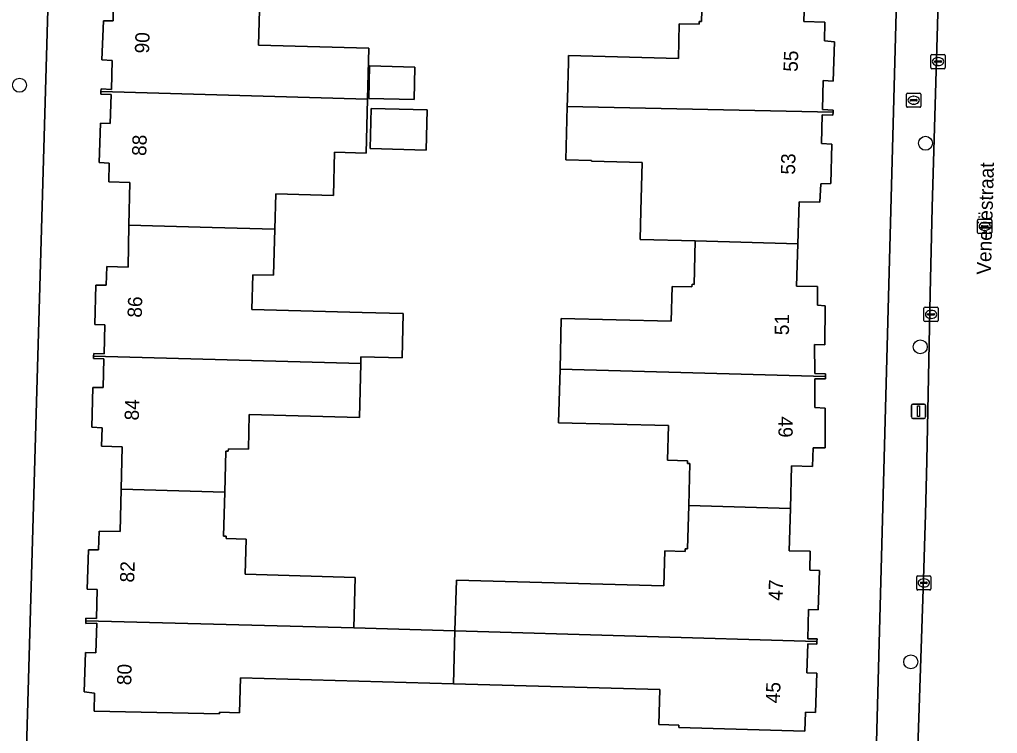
# Model space of a CAD drawing. Extents: x 162082 to 163401, y 388089 to 388636.
# Drawn here: x 162541.9 to 162610.5, y 388380 to 388430.1 of the extents above; entities that cross this region are included whole.
import ezdxf

# ---------------------------------------------------------------- set-up
doc = ezdxf.new("R2010")
doc.units = 0
for name, color, linetype in [('IMGEO_Boom', 7, 'Continuous'), ('IMGEO_Brandkraan', 7, 'Continuous'), ('IMGEO_Erf', 7, 'Continuous'), ('IMGEO_Kolk', 7, 'Continuous'), ('IMGEO_Lichtmast', 7, 'Continuous'), ('IMGEO_Openbare_ruimte_label', 7, 'Continuous'), ('IMGEO_Pand', 7, 'Continuous'), ('IMGEO_Pand_nummerreeks', 7, 'Continuous'), ('IMGEO_Rijbaan_lokaal_open', 7, 'Continuous'), ('IMGEO_Rioolput', 7, 'Continuous'), ('IMGEO_Voetpad_open', 7, 'Continuous')]:
    doc.layers.add(name, color=color, linetype=linetype)

msp = doc.modelspace()

# ---------------------------------------------------------------- linework, layer by layer
at = {"layer": 'IMGEO_Boom'}
for centre in [(162541.9, 388425.468), (162605.489, 388421.397), (162605.12, 388407.11), (162604.452, 388385.007)]:
    msp.add_circle(centre, 0.489, dxfattribs=at)
at = {"layer": 'IMGEO_Brandkraan'}
for p, q in [((162604.158, 388423.994), (162604.158, 388424.846)), ((162604.233, 388424.92), (162605.085, 388424.92)), ((162605.159, 388424.846), (162605.159, 388423.994)), ((162604.417, 388424.414), (162604.417, 388424.426)), ((162604.855, 388424.377), (162604.457, 388424.377)), ((162604.46, 388424.463), (162604.858, 388424.463)), ((162604.669, 388424.14), (162604.644, 388424.14)), ((162604.646, 388424.7), (162604.671, 388424.7)), ((162604.901, 388424.426), (162604.901, 388424.414)), ((162605.085, 388423.92), (162604.233, 388423.92))]:
    msp.add_line(p, q, dxfattribs=at)
for points in [[(162604.158, 388423.994), (162604.158, 388424.846)], [(162604.233, 388424.92), (162605.085, 388424.92)], [(162605.159, 388424.846), (162605.159, 388423.994)], [(162605.085, 388423.92), (162604.233, 388423.92)]]:
    msp.add_lwpolyline(points, dxfattribs=at)
for centre, radius, start, end in [((162604.235, 388424.844), 0.0765, 91.55205, 178.44795), ((162604.235, 388424.844), 0.0765, 91.55205, 178.44795), ((162605.083, 388424.844), 0.0765, 1.55205, 88.44795), ((162605.083, 388424.844), 0.0765, 1.55205, 88.44795), ((162604.457, 388424.423), 0.0403, 85.87752, 175.75265), ((162604.454, 388424.413), 0.0366, 178.93798, 274.71019), ((162604.858, 388424.42), 0.043, 264.86636, 352.45326), ((162604.862, 388424.425), 0.0386, 1.73085, 96.63898), ((162604.235, 388423.996), 0.0765, 181.55205, 268.44795), ((162604.235, 388423.996), 0.0765, 181.55205, 268.44795), ((162605.083, 388423.996), 0.0765, 271.55205, 358.44795), ((162605.083, 388423.996), 0.0765, 271.55205, 358.44795)]:
    msp.add_arc(centre, radius, start, end, dxfattribs=at)
for centre, major_axis, ratio, start_param, end_param in [((162604.645, 388424.42), (-0.387, 0.002), 0.722429, 4.712389, 7.853982), ((162604.67, 388424.42), (-0.39, 0.002), 0.717154, 1.570796, 4.712389)]:
    msp.add_ellipse(centre, major_axis=major_axis, ratio=ratio, start_param=start_param, end_param=end_param, dxfattribs=at)
at = {"layer": 'IMGEO_Erf'}
for points in [[(162544.566, 388454.63), (162544.543, 388453.83), (162544.152, 388440.133), (162546.495, 388440.044), (162546.386, 388437.172), (162546.278, 388437.177), (162544.069, 388437.261), (162542.31, 388375.7), (162595.542, 388374.322), (162601.897, 388374.162), (162603.561, 388435.824)], [(162558.751, 388430.743), (162558.688, 388428.274), (162566.425, 388428.075), (162566.332, 388424.483), (162566.235, 388420.706), (162564.014, 388420.763), (162563.937, 388417.737), (162559.886, 388417.841), (162559.823, 388415.372), (162559.74, 388412.135), (162558.284, 388412.172), (162558.221, 388409.732), (162565.948, 388409.534), (162568.841, 388409.46), (162568.761, 388406.343), (162565.868, 388406.417), (162565.856, 388405.943), (162565.759, 388402.165), (162558.031, 388402.363), (162557.969, 388399.924), (162556.565, 388399.96), (162556.56, 388399.791), (162556.391, 388399.795), (162556.315, 388396.911), (162556.233, 388393.829), (162556.403, 388393.824), (162556.398, 388393.655), (162557.805, 388393.615), (162557.735, 388391.16), (162565.469, 388390.94), (162565.369, 388387.387), (162572.464, 388387.186), (162572.565, 388390.749), (162587.135, 388390.335), (162587.205, 388392.79), (162588.612, 388392.75), (162588.617, 388392.94), (162588.787, 388392.935), (162588.868, 388395.974), (162588.946, 388398.923), (162588.778, 388398.927), (162588.783, 388399.115), (162587.389, 388399.151), (162587.452, 388401.593), (162579.741, 388401.791), (162579.838, 388405.546), (162579.929, 388409.106), (162587.64, 388408.908), (162587.702, 388411.35), (162589.096, 388411.314), (162589.101, 388411.502), (162589.249, 388411.498), (162589.327, 388414.542), (162585.464, 388414.642), (162585.517, 388416.659), (162585.604, 388420.057), (162582.052, 388420.148), (162582.053, 388420.191), (162580.254, 388420.237), (162580.35, 388423.989), (162580.363, 388424.509), (162580.43, 388427.096), (162580.442, 388427.552), (162588.143, 388427.355), (162588.206, 388429.786), (162589.609, 388429.75), (162589.614, 388429.938), (162589.772, 388429.934), (162589.853, 388433.068)], [(162597.041, 388432.876), (162596.948, 388429.933), (162598.43, 388429.889), (162598.393, 388428.574), (162599.107, 388428.521), (162599.013, 388425.762), (162598.301, 388425.792), (162598.262, 388423.766), (162599, 388423.726), (162598.998, 388423.582), (162598.995, 388423.376), (162598.247, 388423.387), (162598.189, 388421.38), (162598.905, 388421.327), (162598.838, 388418.577), (162598.134, 388418.548), (162598.083, 388417.263), (162596.619, 388417.279), (162596.53, 388414.338), (162596.44, 388411.373), (162597.911, 388411.352), (162597.898, 388410.048), (162598.438, 388410), (162598.422, 388407.257), (162597.709, 388407.267), (162597.727, 388405.24), (162598.466, 388405.221), (162598.469, 388405.026), (162598.471, 388404.871), (162597.723, 388404.861), (162597.721, 388402.853), (162598.438, 388402.82), (162598.449, 388400.023), (162597.6, 388400.025), (162597.566, 388398.728), (162596.09, 388398.772), (162596.008, 388395.77), (162595.928, 388392.808), (162597.388, 388392.771), (162597.359, 388391.438), (162598.038, 388391.42), (162597.965, 388388.664), (162597.285, 388388.682), (162597.23, 388386.635), (162597.878, 388386.617), (162597.873, 388386.428), (162597.868, 388386.258), (162597.219, 388386.275), (162597.164, 388384.229), (162597.862, 388384.209), (162597.767, 388381.446), (162597.069, 388381.476), (162597.019, 388380.15), (162588.176, 388380.397), (162588.179, 388380.575), (162586.769, 388380.62), (162586.847, 388383.068), (162572.359, 388383.468), (162557.425, 388383.881), (162557.354, 388381.43), (162555.946, 388381.474), (162555.937, 388381.351), (162547.136, 388381.552), (162547.178, 388382.821), (162546.449, 388382.906), (162546.53, 388385.656), (162547.257, 388385.634), (162547.323, 388387.713), (162546.568, 388387.707), (162546.57, 388387.893), (162546.571, 388388.068), (162547.301, 388388.041), (162547.353, 388390.098), (162546.656, 388390.115), (162546.738, 388392.871), (162547.458, 388392.87), (162547.491, 388394.185), (162548.968, 388394.161), (162549.039, 388397.121), (162549.111, 388400.105), (162547.671, 388400.134), (162547.699, 388401.433), (162546.98, 388401.478), (162547.063, 388404.249), (162547.778, 388404.261), (162547.82, 388406.27), (162547.095, 388406.284), (162547.108, 388406.459), (162547.121, 388406.642), (162547.839, 388406.619), (162547.898, 388408.652), (162547.188, 388408.692), (162547.268, 388411.449), (162547.979, 388411.443), (162548.027, 388412.753), (162549.525, 388412.704), (162549.585, 388415.657), (162549.646, 388418.636), (162548.178, 388418.7), (162548.209, 388420.009), (162547.501, 388420.042), (162547.585, 388422.798), (162548.279, 388422.791), (162548.346, 388424.823), (162547.609, 388424.849), (162547.619, 388425.03), (162547.629, 388425.208), (162548.37, 388425.172), (162548.417, 388427.197), (162547.694, 388427.257), (162547.792, 388429.997), (162548.49, 388429.979), (162548.51, 388431.334)]]:
    msp.add_lwpolyline(points, dxfattribs=at)
for points in [[(162566.416, 388424.547), (162566.475, 388426.83), (162569.655, 388426.748), (162569.596, 388424.465)], [(162566.507, 388421.024), (162566.58, 388423.844), (162570.509, 388423.743), (162570.437, 388420.923)]]:
    msp.add_lwpolyline(points, close=True, dxfattribs=at)
at = {"layer": 'IMGEO_Kolk'}
for p, q in [((162605.867, 388426.703), (162605.867, 388427.555)), ((162605.942, 388427.629), (162606.794, 388427.629)), ((162606.868, 388427.555), (162606.868, 388426.703)), ((162606.126, 388427.123), (162606.126, 388427.135)), ((162606.564, 388427.086), (162606.166, 388427.086)), ((162606.169, 388427.172), (162606.567, 388427.172)), ((162606.378, 388426.849), (162606.353, 388426.849)), ((162606.355, 388427.409), (162606.38, 388427.409)), ((162606.61, 388427.135), (162606.61, 388427.123)), ((162606.794, 388426.629), (162605.942, 388426.629)), ((162605.38, 388408.964), (162605.38, 388409.816)), ((162605.455, 388409.89), (162606.307, 388409.89)), ((162606.381, 388409.816), (162606.381, 388408.964)), ((162605.639, 388409.384), (162605.639, 388409.396)), ((162606.077, 388409.347), (162605.679, 388409.347)), ((162605.682, 388409.433), (162606.08, 388409.433)), ((162605.891, 388409.11), (162605.866, 388409.11)), ((162605.868, 388409.67), (162605.893, 388409.67)), ((162606.123, 388409.396), (162606.123, 388409.384)), ((162606.307, 388408.89), (162605.455, 388408.89)), ((162604.868, 388390.126), (162604.868, 388390.978)), ((162604.943, 388391.052), (162605.795, 388391.052)), ((162605.127, 388390.546), (162605.127, 388390.558)), ((162605.565, 388390.509), (162605.167, 388390.509)), ((162605.17, 388390.595), (162605.568, 388390.595)), ((162605.356, 388390.832), (162605.381, 388390.832)), ((162605.611, 388390.558), (162605.611, 388390.546)), ((162605.869, 388390.978), (162605.869, 388390.126)), ((162605.795, 388390.052), (162604.943, 388390.052)), ((162605.379, 388390.272), (162605.354, 388390.272))]:
    msp.add_line(p, q, dxfattribs=at)
for points in [[(162605.867, 388426.703), (162605.867, 388427.555)], [(162605.942, 388427.629), (162606.794, 388427.629)], [(162606.868, 388427.555), (162606.868, 388426.703)], [(162606.794, 388426.629), (162605.942, 388426.629)], [(162605.38, 388408.964), (162605.38, 388409.816)], [(162605.455, 388409.89), (162606.307, 388409.89)], [(162606.381, 388409.816), (162606.381, 388408.964)], [(162606.307, 388408.89), (162605.455, 388408.89)], [(162604.868, 388390.126), (162604.868, 388390.978)], [(162604.943, 388391.052), (162605.795, 388391.052)], [(162605.869, 388390.978), (162605.869, 388390.126)], [(162605.795, 388390.052), (162604.943, 388390.052)]]:
    msp.add_lwpolyline(points, dxfattribs=at)
for centre, radius, start, end in [((162605.944, 388427.553), 0.0765, 91.55205, 178.44795), ((162605.944, 388427.553), 0.0765, 91.55205, 178.44795), ((162606.792, 388427.553), 0.0765, 1.55205, 88.44795), ((162606.792, 388427.553), 0.0765, 1.55205, 88.44795), ((162606.166, 388427.132), 0.0403, 85.87752, 175.75265), ((162606.163, 388427.122), 0.0366, 178.93798, 274.71019), ((162606.567, 388427.129), 0.043, 264.86636, 352.45326), ((162606.571, 388427.134), 0.0386, 1.73085, 96.63898), ((162605.944, 388426.705), 0.0765, 181.55205, 268.44795), ((162605.944, 388426.705), 0.0765, 181.55205, 268.44795), ((162606.792, 388426.705), 0.0765, 271.55205, 358.44795), ((162606.792, 388426.705), 0.0765, 271.55205, 358.44795), ((162605.457, 388409.814), 0.0765, 91.55205, 178.44795), ((162605.457, 388409.814), 0.0765, 91.55205, 178.44795), ((162606.305, 388409.814), 0.0765, 1.55205, 88.44795), ((162606.305, 388409.814), 0.0765, 1.55205, 88.44795), ((162605.679, 388409.393), 0.0403, 85.87752, 175.75265), ((162605.676, 388409.383), 0.0366, 178.93798, 274.71019), ((162606.08, 388409.39), 0.043, 264.86636, 352.45326), ((162606.084, 388409.395), 0.0386, 1.73085, 96.63898), ((162605.457, 388408.966), 0.0765, 181.55205, 268.44795), ((162605.457, 388408.966), 0.0765, 181.55205, 268.44795), ((162606.305, 388408.966), 0.0765, 271.55205, 358.44795), ((162606.305, 388408.966), 0.0765, 271.55205, 358.44795), ((162604.945, 388390.976), 0.0765, 91.55205, 178.44795), ((162604.945, 388390.976), 0.0765, 91.55205, 178.44795), ((162605.167, 388390.555), 0.0403, 85.87752, 175.75265), ((162605.164, 388390.545), 0.0366, 178.93798, 274.71019), ((162605.568, 388390.552), 0.043, 264.86636, 352.45326), ((162605.572, 388390.557), 0.0386, 1.73085, 96.63898), ((162605.793, 388390.976), 0.0765, 1.55205, 88.44795), ((162605.793, 388390.976), 0.0765, 1.55205, 88.44795), ((162604.945, 388390.128), 0.0765, 181.55205, 268.44795), ((162604.945, 388390.128), 0.0765, 181.55205, 268.44795), ((162605.793, 388390.128), 0.0765, 271.55205, 358.44795), ((162605.793, 388390.128), 0.0765, 271.55205, 358.44795)]:
    msp.add_arc(centre, radius, start, end, dxfattribs=at)
for centre, major_axis, ratio, start_param, end_param in [((162606.354, 388427.129), (-0.387, 0.002), 0.722429, 4.712389, 7.853982), ((162606.379, 388427.129), (-0.39, 0.002), 0.717154, 1.570796, 4.712389), ((162605.867, 388409.39), (-0.387, 0.002), 0.722429, 4.712389, 7.853982), ((162605.892, 388409.39), (-0.39, 0.002), 0.717154, 1.570796, 4.712389), ((162605.355, 388390.552), (-0.387, 0.002), 0.722429, 4.712389, 7.853982), ((162605.38, 388390.552), (-0.39, 0.002), 0.717154, 1.570796, 4.712389)]:
    msp.add_ellipse(centre, major_axis=major_axis, ratio=ratio, start_param=start_param, end_param=end_param, dxfattribs=at)
at = {"layer": 'IMGEO_Lichtmast'}
for p, q in [((162604.503, 388402.191), (162604.503, 388402.991)), ((162604.503, 388402.991), (162604.503, 388402.191)), ((162604.603, 388403.091), (162605.393, 388403.091)), ((162605.393, 388403.091), (162604.603, 388403.091)), ((162605.493, 388402.991), (162605.493, 388402.191)), ((162605.493, 388402.191), (162605.493, 388402.991)), ((162605.393, 388402.091), (162604.603, 388402.091)), ((162604.603, 388402.091), (162605.393, 388402.091))]:
    msp.add_line(p, q, dxfattribs=at)
msp.add_lwpolyline([(162604.923, 388402.966), (162605.073, 388402.966), (162605.073, 388402.216), (162604.923, 388402.216), (162604.923, 388402.966)], dxfattribs=at)
for centre, start, end in [((162604.603, 388402.991), 90, 180), ((162604.603, 388402.991), 90, 180), ((162605.393, 388402.991), 0, 90), ((162605.393, 388402.991), 360, 90), ((162604.603, 388402.191), 180, 270), ((162604.603, 388402.191), 180, 270), ((162605.393, 388402.191), 270, 0), ((162605.393, 388402.191), 270, 0)]:
    msp.add_arc(centre, 0.1, start, end, dxfattribs=at)
at = {"layer": 'IMGEO_Pand'}
for points in [[(162555.865, 388433.986), (162554.898, 388434.009), (162550.095, 388434.125), (162550.025, 388431.266), (162548.51, 388431.334), (162548.49, 388429.979), (162547.792, 388429.997), (162547.694, 388427.257), (162548.417, 388427.197), (162548.37, 388425.172), (162547.629, 388425.208), (162547.619, 388425.03), (162566.332, 388424.483), (162566.425, 388428.075), (162558.688, 388428.274), (162558.751, 388430.743), (162557.337, 388430.78), (162557.342, 388430.969), (162555.788, 388431.009)], [(162599.107, 388428.521), (162598.393, 388428.574), (162598.43, 388429.889), (162596.948, 388429.933), (162597.041, 388432.876), (162592.221, 388433.005), (162589.853, 388433.068), (162589.772, 388429.934), (162589.614, 388429.938), (162589.609, 388429.75), (162588.206, 388429.786), (162588.143, 388427.355), (162580.442, 388427.552), (162580.43, 388427.096), (162580.363, 388424.509), (162580.35, 388423.989), (162598.998, 388423.582), (162599, 388423.726), (162598.262, 388423.766), (162598.301, 388425.792), (162599.013, 388425.762)], [(162566.416, 388424.547), (162569.596, 388424.465), (162569.655, 388426.748), (162566.475, 388426.83)], [(162566.235, 388420.706), (162566.332, 388424.483), (162547.619, 388425.03), (162547.609, 388424.849), (162548.346, 388424.823), (162548.279, 388422.791), (162547.585, 388422.798), (162547.501, 388420.042), (162548.209, 388420.009), (162548.178, 388418.7), (162549.646, 388418.636), (162549.585, 388415.657), (162555.419, 388415.494), (162559.823, 388415.372), (162559.886, 388417.841), (162563.937, 388417.737), (162564.014, 388420.763)], [(162566.507, 388421.024), (162570.437, 388420.923), (162570.509, 388423.743), (162566.58, 388423.844)], [(162598.905, 388421.327), (162598.189, 388421.38), (162598.247, 388423.387), (162598.995, 388423.376), (162598.998, 388423.582), (162580.35, 388423.989), (162580.254, 388420.237), (162582.053, 388420.191), (162582.052, 388420.148), (162585.604, 388420.057), (162585.517, 388416.659), (162585.464, 388414.642), (162589.327, 388414.542), (162596.53, 388414.338), (162596.619, 388417.279), (162598.083, 388417.263), (162598.134, 388418.548), (162598.838, 388418.577)], [(162558.284, 388412.172), (162559.74, 388412.135), (162559.823, 388415.372), (162555.419, 388415.494), (162549.585, 388415.657), (162549.525, 388412.704), (162548.027, 388412.753), (162547.979, 388411.443), (162547.268, 388411.449), (162547.188, 388408.692), (162547.898, 388408.652), (162547.839, 388406.619), (162547.121, 388406.642), (162547.108, 388406.459), (162565.856, 388405.943), (162565.868, 388406.417), (162568.761, 388406.343), (162568.841, 388409.46), (162565.948, 388409.534), (162558.221, 388409.732)], [(162589.327, 388414.542), (162589.249, 388411.498), (162589.101, 388411.502), (162589.096, 388411.314), (162587.702, 388411.35), (162587.64, 388408.908), (162579.929, 388409.106), (162579.838, 388405.546), (162598.469, 388405.026), (162598.466, 388405.221), (162597.727, 388405.24), (162597.709, 388407.267), (162598.422, 388407.257), (162598.438, 388410), (162597.898, 388410.048), (162597.911, 388411.352), (162596.44, 388411.373), (162596.53, 388414.338)], [(162549.039, 388397.121), (162556.315, 388396.911), (162556.391, 388399.795), (162556.56, 388399.791), (162556.565, 388399.96), (162557.969, 388399.924), (162558.031, 388402.363), (162565.759, 388402.165), (162565.856, 388405.943), (162547.108, 388406.459), (162547.095, 388406.284), (162547.82, 388406.27), (162547.778, 388404.261), (162547.063, 388404.249), (162546.98, 388401.478), (162547.699, 388401.433), (162547.671, 388400.134), (162549.111, 388400.105)], [(162579.838, 388405.546), (162579.741, 388401.791), (162587.452, 388401.593), (162587.389, 388399.151), (162588.783, 388399.115), (162588.778, 388398.927), (162588.946, 388398.923), (162588.868, 388395.974), (162596.008, 388395.77), (162596.09, 388398.772), (162597.566, 388398.728), (162597.6, 388400.025), (162598.449, 388400.023), (162598.438, 388402.82), (162597.721, 388402.853), (162597.723, 388404.861), (162598.471, 388404.871), (162598.469, 388405.026)], [(162549.039, 388397.121), (162548.968, 388394.161), (162547.491, 388394.185), (162547.458, 388392.87), (162546.738, 388392.871), (162546.656, 388390.115), (162547.353, 388390.098), (162547.301, 388388.041), (162546.571, 388388.068), (162546.57, 388387.893), (162565.369, 388387.387), (162565.469, 388390.94), (162557.735, 388391.16), (162557.805, 388393.615), (162556.398, 388393.655), (162556.403, 388393.824), (162556.233, 388393.829), (162556.315, 388396.911)], [(162572.464, 388387.186), (162597.873, 388386.428), (162597.878, 388386.617), (162597.23, 388386.635), (162597.285, 388388.682), (162597.965, 388388.664), (162598.038, 388391.42), (162597.359, 388391.438), (162597.388, 388392.771), (162595.928, 388392.808), (162596.008, 388395.77), (162588.868, 388395.974), (162588.787, 388392.935), (162588.617, 388392.94), (162588.612, 388392.75), (162587.205, 388392.79), (162587.135, 388390.335), (162572.565, 388390.749)], [(162572.464, 388387.186), (162565.369, 388387.387), (162546.57, 388387.893), (162546.568, 388387.707), (162547.323, 388387.713), (162547.257, 388385.634), (162546.53, 388385.656), (162546.449, 388382.906), (162547.178, 388382.821), (162547.136, 388381.552), (162555.937, 388381.351), (162555.946, 388381.474), (162557.354, 388381.43), (162557.425, 388383.881), (162572.359, 388383.468)], [(162572.464, 388387.186), (162572.359, 388383.468), (162586.847, 388383.068), (162586.769, 388380.62), (162588.179, 388380.575), (162588.176, 388380.397), (162597.019, 388380.15), (162597.069, 388381.476), (162597.767, 388381.446), (162597.862, 388384.209), (162597.164, 388384.229), (162597.219, 388386.275), (162597.868, 388386.258), (162597.873, 388386.428)]]:
    msp.add_lwpolyline(points, close=True, dxfattribs=at)
at = {"layer": 'IMGEO_Rijbaan_lokaal_open'}
msp.add_lwpolyline([(162613.718, 388441.426), (162613.97, 388449.157), (162606.936, 388449.257), (162606.593, 388439.749), (162606.503, 388435.662), (162606.338, 388429.695), (162605.965, 388416.886), (162605.815, 388410.859), (162605.583, 388399.107), (162605.48, 388395.34), (162605.461, 388394.621), (162605.357, 388390.813), (162604.951, 388379.009), (162604.81, 388375.778), (162611.897, 388375.594)], close=True, dxfattribs=at)
at = {"layer": 'IMGEO_Rioolput'}
for p, q in [((162609.144, 388415.136), (162609.144, 388415.988)), ((162609.219, 388416.062), (162610.071, 388416.062)), ((162610.145, 388415.988), (162610.145, 388415.136)), ((162609.403, 388415.556), (162609.403, 388415.568)), ((162609.841, 388415.519), (162609.443, 388415.519)), ((162609.446, 388415.605), (162609.844, 388415.605)), ((162609.655, 388415.282), (162609.63, 388415.282)), ((162609.632, 388415.842), (162609.657, 388415.842)), ((162609.887, 388415.568), (162609.887, 388415.556)), ((162610.071, 388415.062), (162609.219, 388415.062))]:
    msp.add_line(p, q, dxfattribs=at)
for points in [[(162609.144, 388415.136), (162609.144, 388415.988)], [(162609.219, 388416.062), (162610.071, 388416.062)], [(162610.145, 388415.988), (162610.145, 388415.136)], [(162610.071, 388415.062), (162609.219, 388415.062)]]:
    msp.add_lwpolyline(points, dxfattribs=at)
for centre, radius, start, end in [((162609.221, 388415.986), 0.0765, 91.55205, 178.44795), ((162609.221, 388415.986), 0.0765, 91.55205, 178.44795), ((162610.069, 388415.986), 0.0765, 1.55205, 88.44795), ((162610.069, 388415.986), 0.0765, 1.55205, 88.44795), ((162609.443, 388415.565), 0.0403, 85.87752, 175.75265), ((162609.44, 388415.555), 0.0366, 178.93798, 274.71019), ((162609.844, 388415.562), 0.043, 264.86636, 352.45326), ((162609.848, 388415.567), 0.0386, 1.73085, 96.63898), ((162609.221, 388415.138), 0.0765, 181.55205, 268.44795), ((162609.221, 388415.138), 0.0765, 181.55205, 268.44795), ((162610.069, 388415.138), 0.0765, 271.55205, 358.44795), ((162610.069, 388415.138), 0.0765, 271.55205, 358.44795)]:
    msp.add_arc(centre, radius, start, end, dxfattribs=at)
for centre, major_axis, ratio, start_param, end_param in [((162609.631, 388415.562), (-0.387, 0.002), 0.722429, 4.712389, 7.853982), ((162609.656, 388415.562), (-0.39, 0.002), 0.717154, 1.570796, 4.712389)]:
    msp.add_ellipse(centre, major_axis=major_axis, ratio=ratio, start_param=start_param, end_param=end_param, dxfattribs=at)
at = {"layer": 'IMGEO_Voetpad_open'}
for points in [[(162605.965, 388416.886), (162606.338, 388429.695), (162606.503, 388435.662), (162606.593, 388439.749), (162606.936, 388449.257), (162607.013, 388451.628), (162607.056, 388452.794), (162607.099, 388454.579), (162603.293, 388454.618)], [(162604.006, 388452.295), (162603.756, 388443.021), (162603.561, 388435.824), (162601.897, 388374.162), (162601.825, 388371.72), (162605.084, 388371.576)], [(162540.853, 388373.46), (162541.839, 388373.434), (162542.25, 388373.416), (162542.31, 388375.7), (162544.069, 388437.261)], [(162604.762, 388374.461), (162604.81, 388375.778), (162604.951, 388379.009), (162605.357, 388390.813), (162605.461, 388394.621), (162605.48, 388395.34), (162605.583, 388399.107), (162605.815, 388410.859), (162605.965, 388416.886)]]:
    msp.add_lwpolyline(points, dxfattribs=at)

# ---------------------------------------------------------------- texts
at = {"layer": 'IMGEO_Openbare_ruimte_label'}
msp.add_text('Venetiëstraat', height=1, rotation=88.39614, dxfattribs=at).set_placement((162610.076, 388412.164))
at = {"layer": 'IMGEO_Pand_nummerreeks'}
for s, rotation, p in [('90', 87.95161, (162550.992, 388427.687)), ('55', 88.04642, (162596.513, 388426.401)), ('88', 88.25269, (162550.796, 388420.498)), ('53', 88.60219, (162596.332, 388419.188)), ('86', 88.33863, (162550.483, 388409.15)), ('51', 89.66579, (162595.906, 388407.93)), ('84', 88.28433, (162550.275, 388401.939)), ('49', 270.22533, (162595.161, 388402.234)), ('82', 88.29577, (162549.951, 388390.566)), ('47', 88.48272, (162595.461, 388389.283)), ('80', 88.31287, (162549.744, 388383.361)), ('45', 88.03078, (162595.267, 388382.089))]:
    msp.add_text(s, height=1, rotation=rotation, dxfattribs=at).set_placement(p)

doc.saveas('drawing.dxf')
